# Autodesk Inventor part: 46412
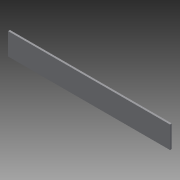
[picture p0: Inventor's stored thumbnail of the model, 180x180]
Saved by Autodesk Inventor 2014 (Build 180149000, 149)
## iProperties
Shininess: 20.0
Length Units: 11272
Angle Units: 11279
Time Units: 11290
Mass Units: 11286
Length Display Precision: 3
Angle Display Precision: 2
Company: Autodesk, Inc.
Part Number: 46412
Document SubType Name: Modeling
Material: Generic
Created: 2003-01
Designer: Autodesk, Inc.
Description: DECAL;A; ACCUMULATOR PRESS
Density: 1 g/cm^3
Sheet Metal Rule: Default
Mass: 4.22479 g
Surface Area: 58.266 cm^2
Volume: 4.22479 cm^3
Appearance: Default
Density: 0.0
Volumn: 0.0
Area: 0.0
PropertySet Name: Model Information
Control State: 0
Master: False
Checked Out: False
Last Check In By: JT
Last Check In Date: 2003-06-20
Title: DECAL;A; ACCUMULATOR PRESS
Author: Autodesk, Inc.
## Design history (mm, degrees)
sketch "Sketch1"
  geometry: L1 (0, 0)-(139.7, 0); L2 (139.7, 0)-(139.7, 19.05); L3 (139.7, 19.05)-(0, 19.05); L4 (0, 19.05)-(0, 0)
  constraints: 8 end point, 2 parallel, 1 horizontal, 1 perpendicular
  dimensions: "d3" = 19.05 distance of L3.end L1.start; "d4" = 139.7 distance of L1.start L1.end
extrude "Extrusion2" new body sketch "Sketch1" distance "d5" = 1.5875; taper "d6" = 0 deg
body "Solid1"
other parameters: "Thickness" = 6.35, "BendRadius" = 6.35, "BendReliefWidth" = 6.35 (= Thickness), "BendReliefDepth" = 3.175 (= 0.5 x Thickness), "CornerReliefSize" = 25.4 (= 4 x Thickness), "SeamGap" = 0.00508, "MinimumRemnant" = 12.7 (= 2 x Thickness), "TransitionRadius" = 6.35 (= BendRadius), "JacobiRadiusSize" = 6.35 (= Thickness), "GapSize" = 6.35 (= Thickness)
